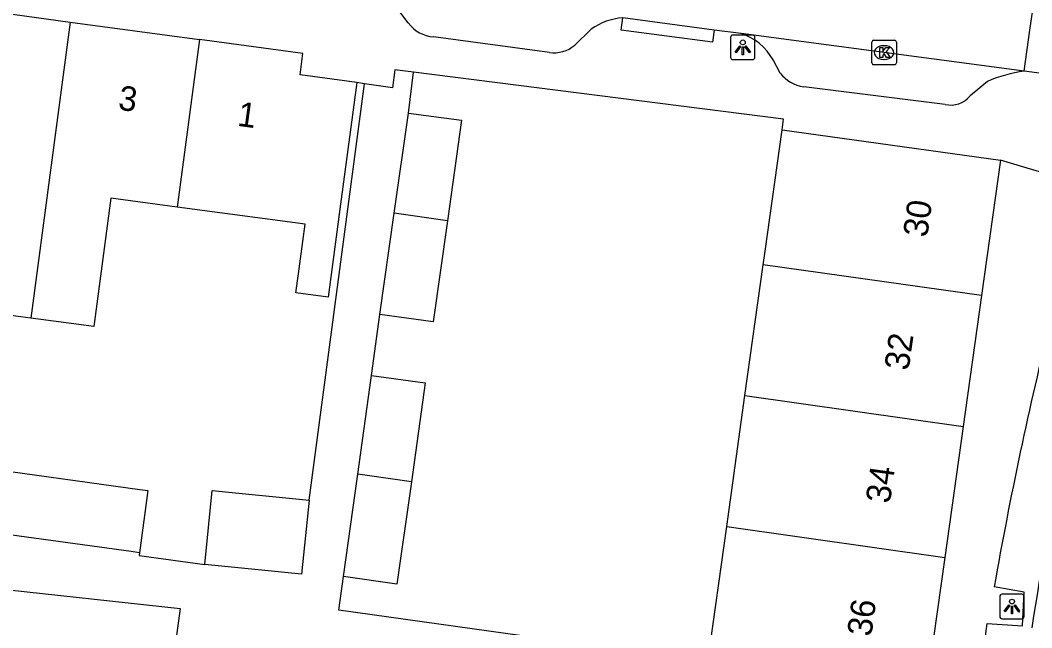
# Model space of a CAD drawing. Extents: x 161845 to 162341, y 381620 to 382158.
# Drawn here: x 162001.22 to 162042.46, y 381669.37 to 381694.14 of the extents above; entities that cross this region are included whole.
import ezdxf

# ---------------------------------------------------------------- set-up
doc = ezdxf.new("R2010")
doc.units = 0
for name, color, linetype in [('IMGEO_Kolk', 7, 'Continuous'), ('IMGEO_Lichtpunt', 7, 'Continuous'), ('IMGEO_Muur', 7, 'Continuous'), ('IMGEO_Pand', 7, 'Continuous'), ('IMGEO_Pand_nummerreeks', 7, 'Continuous'), ('IMGEO_Rijbaan_lokaal_open', 7, 'Continuous'), ('IMGEO_Voetpad_open', 7, 'Continuous')]:
    doc.layers.add(name, color=color, linetype=linetype)

msp = doc.modelspace()

# ---------------------------------------------------------------- linework, layer by layer
at = {"layer": 'IMGEO_Kolk'}
for p, q in [((162035.936, 381692.399), (162035.936, 381693.251)), ((162036.011, 381693.325), (162036.863, 381693.325)), ((162036.937, 381693.251), (162036.937, 381692.399)), ((162036.424, 381693.105), (162036.449, 381693.105)), ((162036.447, 381692.545), (162036.422, 381692.545)), ((162036.863, 381692.325), (162036.011, 381692.325))]:
    msp.add_line(p, q, dxfattribs=at)
for points in [[(162035.936, 381692.399), (162035.936, 381693.251)], [(162036.011, 381693.325), (162036.863, 381693.325)], [(162036.937, 381693.251), (162036.937, 381692.399)], [(162036.257, 381693.025), (162036.38, 381693.025), (162036.38, 381692.874), (162036.51, 381693.025), (162036.674, 381693.025), (162036.528, 381692.874), (162036.681, 381692.625), (162036.529, 381692.625), (162036.444, 381692.789), (162036.38, 381692.722), (162036.38, 381692.625), (162036.257, 381692.625), (162036.257, 381693.025)], [(162036.863, 381692.325), (162036.011, 381692.325)]]:
    msp.add_lwpolyline(points, dxfattribs=at)
for centre, start, end in [((162036.013, 381693.249), 91.552, 178.448), ((162036.013, 381693.249), 91.552, 178.448), ((162036.861, 381693.249), 1.552, 88.448), ((162036.861, 381693.249), 1.552, 88.448), ((162036.013, 381692.401), 181.552, 268.448), ((162036.013, 381692.401), 181.552, 268.448), ((162036.861, 381692.401), 271.552, 358.448), ((162036.861, 381692.401), 271.552, 358.448)]:
    msp.add_arc(centre, 0.0765, start, end, dxfattribs=at)
for centre, major_axis, ratio, start_param, end_param in [((162036.423, 381692.825), (-0.387, 0.002), 0.722429, 4.712389, 7.853982), ((162036.448, 381692.825), (-0.39, 0.002), 0.717154, 1.570796, 4.712389)]:
    msp.add_ellipse(centre, major_axis=major_axis, ratio=ratio, start_param=start_param, end_param=end_param, dxfattribs=at)
at = {"layer": 'IMGEO_Lichtpunt'}
for p, q in [((162030.176, 381693.44), (162030.176, 381692.633)), ((162030.176, 381693.44), (162030.176, 381692.633)), ((162031.078, 381693.535), (162030.27, 381693.535)), ((162031.078, 381693.535), (162030.27, 381693.535)), ((162031.172, 381692.633), (162031.172, 381693.44)), ((162031.172, 381692.633), (162031.172, 381693.44)), ((162030.27, 381692.539), (162031.078, 381692.539)), ((162030.27, 381692.539), (162031.078, 381692.539)), ((162041.152, 381670.637), (162041.152, 381669.83)), ((162041.152, 381670.637), (162041.152, 381669.83)), ((162042.054, 381670.732), (162041.246, 381670.732)), ((162042.054, 381670.732), (162041.246, 381670.732)), ((162042.148, 381669.83), (162042.148, 381670.637)), ((162042.148, 381669.83), (162042.148, 381670.637)), ((162041.246, 381669.736), (162042.054, 381669.736)), ((162041.246, 381669.736), (162042.054, 381669.736))]:
    msp.add_line(p, q, dxfattribs=at)
for points in [[(162030.55, 381693.104), (162030.589, 381693.076), (162030.401, 381692.814), (162030.363, 381692.841), (162030.55, 381693.104)], [(162030.652, 381693.056), (162030.699, 381693.056), (162030.699, 381692.734), (162030.652, 381692.734), (162030.652, 381693.056)], [(162030.762, 381693.076), (162030.8, 381693.103), (162030.987, 381692.841), (162030.948, 381692.813), (162030.762, 381693.076)], [(162041.526, 381670.301), (162041.565, 381670.273), (162041.377, 381670.011), (162041.339, 381670.038), (162041.526, 381670.301)], [(162041.628, 381670.253), (162041.675, 381670.253), (162041.675, 381669.931), (162041.628, 381669.931), (162041.628, 381670.253)], [(162041.738, 381670.273), (162041.776, 381670.3), (162041.963, 381670.038), (162041.924, 381670.01), (162041.738, 381670.273)]]:
    msp.add_lwpolyline(points, dxfattribs=at)
for centre in [(162030.675, 381693.238), (162041.651, 381670.435)]:
    msp.add_circle(centre, 0.0994, dxfattribs=at)
for centre, start, end in [((162030.27, 381693.44), 90, 180), ((162030.27, 381693.44), 90, 180), ((162031.078, 381693.44), 0, 90), ((162031.078, 381693.44), 0, 90), ((162030.27, 381692.633), 180, 270), ((162030.27, 381692.633), 180, 270), ((162031.078, 381692.633), 270, 0), ((162031.078, 381692.633), 270, 360), ((162041.246, 381670.637), 90, 180), ((162041.246, 381670.637), 90, 180), ((162042.054, 381670.637), 0, 90), ((162042.054, 381670.637), 0, 90), ((162041.246, 381669.83), 180, 270), ((162041.246, 381669.83), 180, 270), ((162042.054, 381669.83), 270, 0), ((162042.054, 381669.83), 270, 360)]:
    msp.add_arc(centre, 0.0946, start, end, dxfattribs=at)
at = {"layer": 'IMGEO_Muur'}
msp.add_lwpolyline([(162032.275, 381689.671), (162032.337, 381690.112), (162017.248, 381692.026)], dxfattribs=at)
at = {"layer": 'IMGEO_Pand'}
for points in [[(161998.113, 381694.765), (162000, 381694.51), (162003.254, 381694.07)], [(162003.254, 381694.07), (162001.647, 381681.994)], [(162003.254, 381694.07), (162008.529, 381693.356)], [(162008.529, 381693.356), (162007.619, 381686.521)], [(162014.938, 381691.603), (162012.629, 381691.911), (162012.746, 381692.786), (162008.529, 381693.356)], [(162014.938, 381691.603), (162014.277, 381686.647), (162013.771, 381682.849), (162012.455, 381683.024), (162012.558, 381683.796), (162012.64, 381684.411), (162012.829, 381685.826), (162007.619, 381686.521)], [(162016.464, 381686.268), (162017.041, 381690.355)], [(162017.041, 381690.355), (162019.212, 381690.063), (162018.632, 381685.965)], [(162031.508, 381684.166), (162031.585, 381684.719), (162032.275, 381689.671)], [(162032.275, 381689.671), (162041.184, 381688.441)], [(162041.184, 381688.441), (162040.411, 381682.922)], [(162001.647, 381681.994), (162000, 381682.215), (161999.271, 381682.313), (161999.967, 381687.532), (161997.184, 381687.904)], [(162007.619, 381686.521), (162004.909, 381686.882), (162004.212, 381681.651), (162001.647, 381681.994)], [(162015.882, 381682.142), (162016.464, 381686.268)], [(162018.632, 381685.965), (162016.464, 381686.268)], [(162018.632, 381685.965), (162018.05, 381681.849), (162015.882, 381682.142)], [(162030.766, 381678.841), (162031.508, 381684.166)], [(162040.411, 381682.922), (162031.508, 381684.166)], [(162040.411, 381682.922), (162039.661, 381677.574)], [(162014.977, 381675.628), (162015.536, 381679.655)], [(162015.536, 381679.655), (162017.73, 381679.359), (162017.163, 381675.318)], [(162030.021, 381673.496), (162030.766, 381678.841)], [(162030.766, 381678.841), (162039.661, 381677.574)], [(162039.661, 381677.574), (162038.913, 381672.236)], [(162000.815, 381675.738), (162006.094, 381675.009), (162006.426, 381674.963), (162006.076, 381672.428)], [(162014.398, 381671.454), (162014.977, 381675.628)], [(162017.163, 381675.318), (162014.977, 381675.628)], [(162017.163, 381675.318), (162016.576, 381671.14), (162014.398, 381671.454)], [(162008.739, 381671.948), (162009.038, 381674.964), (162012.991, 381674.571)], [(162012.991, 381674.571), (162012.691, 381671.555), (162008.739, 381671.948)], [(162029.252, 381667.982), (162030.021, 381673.496)], [(162030.021, 381673.496), (162038.913, 381672.236)], [(162006.076, 381672.428), (162005.744, 381672.474), (162000.477, 381673.201)], [(162038.913, 381672.236), (162038.143, 381666.74)]]:
    msp.add_lwpolyline(points, dxfattribs=at)
at = {"layer": 'IMGEO_Rijbaan_lokaal_open'}
for points in [[(162042.152, 381692.068), (162042.384, 381693.733), (162042.617, 381695.408)], [(162029.512, 381693.742), (162025.782, 381694.237)], [(162030.604, 381693.598), (162029.512, 381693.742)], [(162042.152, 381692.068), (162030.604, 381693.598)], [(162044.609, 381691.743), (162042.152, 381692.068)]]:
    msp.add_lwpolyline(points, dxfattribs=at)
msp.add_arc((162151.355, 381652.693), 110.166, 163.30609, 171.29454, dxfattribs=at)
at = {"layer": 'IMGEO_Voetpad_open'}
for points in [[(162017.04, 381694.032), (162016.326, 381694.981)], [(162029.512, 381693.742), (162029.445, 381693.247), (162025.724, 381693.74), (162025.782, 381694.237)], [(162024.493, 381693.772), (162023.823, 381693.122)], [(162022.796, 381692.825), (162018.071, 381693.465)], [(162032.205, 381691.99), (162031.911, 381692.522)], [(162017.248, 381692.026), (162016.489, 381692.122), (162016.395, 381691.381), (162015.256, 381691.555)], [(162017.041, 381690.355), (162017.248, 381692.026)], [(162032.275, 381689.671), (162032.337, 381690.112), (162017.248, 381692.026)], [(162015.256, 381691.555), (162014.938, 381691.603)], [(162040.648, 381691.645), (162039.94, 381691.058)], [(162012.991, 381674.571), (162015.256, 381691.555)], [(162038.926, 381690.711), (162033.16, 381691.423)], [(162046, 381686.994), (162041.184, 381688.441)], [(162015.536, 381679.655), (162015.882, 381682.142)], [(162006.076, 381672.428), (162006.066, 381672.317), (162008.739, 381671.948)], [(162029.252, 381667.982), (162014.207, 381670.084), (162014.398, 381671.454)], [(161999.987, 381670.997), (162007.737, 381670.151), (162006.607, 381661.854)], [(162037.603, 381646.528), (162040.641, 381669.544), (162042.076, 381669.449), (162042.146, 381670.82), (162040.926, 381671.043)]]:
    msp.add_lwpolyline(points, dxfattribs=at)
for centre, radius, start, end in [((162025.923, 381691.828), 2.413, 93.3404, 126.3329), ((162018.156, 381694.841), 1.379, 215.9355, 266.4472), ((162029.949, 381691.471), 2.225, 28.1789, 72.8947), ((162022.971, 381694.145), 1.331, 262.458, 309.8009), ((162033.373, 381692.869), 1.462, 216.9741, 261.6292), ((162042.999, 381686.171), 5.957, 98.1735, 113.2438), ((162039.162, 381691.675), 0.993, 256.2293, 321.5536), ((162203.621, 381642.33), 165.209, 166.11255, 169.99138)]:
    msp.add_arc(centre, radius, start, end, dxfattribs=at)

# ---------------------------------------------------------------- texts
at = {"layer": 'IMGEO_Pand_nummerreeks'}
for s, rotation, p in [('3', 352.2959, (162005.179, 381690.5)), ('1', 352.2937, (162010.038, 381689.841)), ('30', 82.023, (162038.194, 381685.262)), ('32', 82.023, (162037.434, 381679.831)), ('34', 82.023, (162036.673, 381674.408)), ('36', 82.023, (162035.913, 381668.983))]:
    msp.add_text(s, height=1, rotation=rotation, dxfattribs=at).set_placement(p)

doc.saveas('drawing.dxf')
